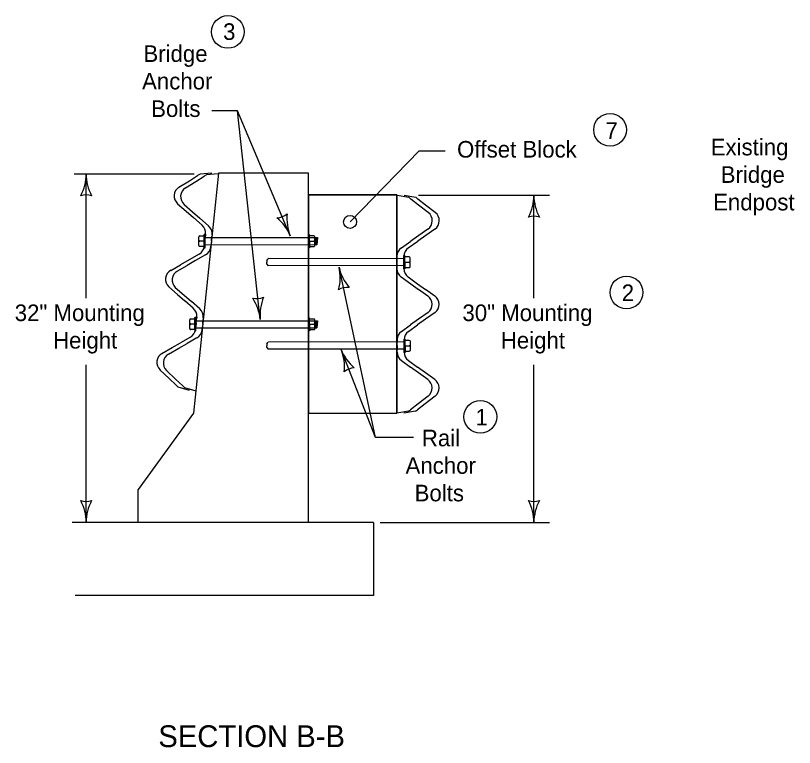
# Model space of a CAD drawing. Extents: x -2137026 to -2131464, y -2138478 to -2136524.
# Drawn here: x -2136255 to -2135542, y -2137286 to -2136616 of the extents above; entities that cross this region are included whole.
import ezdxf

# ---------------------------------------------------------------- set-up
doc = ezdxf.new("R2010")
doc.units = 0
for name, color, linetype in [('conPaving', 7, 'Continuous'), ('Level 2', 7, 'Continuous'), ('Level 3', 7, 'Continuous'), ('Level 9', 7, 'Continuous')]:
    doc.layers.add(name, color=color, linetype=linetype)

msp = doc.modelspace()

# ---------------------------------------------------------------- linework, layer by layer
at = {"layer": 'conPaving'}
for p, q in [((-2135980.49, -2136818.99), (-2135980.97, -2136825.47)), ((-2135979.93, -2136818.99), (-2135980.42, -2136825.47)), ((-2135979.38, -2136818.99), (-2135979.86, -2136825.47)), ((-2135978.82, -2136818.99), (-2135979.31, -2136825.47)), ((-2135980.52, -2136895.16), (-2135981, -2136901.64)), ((-2135979.96, -2136895.16), (-2135980.44, -2136901.64)), ((-2135979.4, -2136895.16), (-2135979.89, -2136901.64)), ((-2135978.89, -2136895.16), (-2135979.37, -2136901.64))]:
    msp.add_line(p, q, dxfattribs=at)
at = {"layer": 'Level 2'}
for p, q in [((-2136051.92, -2136702.87), (-2136075.52, -2136702.87)), ((-2136003.7, -2136817.5), (-2136051.92, -2136702.87)), ((-2136031.2, -2136893.97), (-2136051.92, -2136702.87)), ((-2135949.03, -2136804.59), (-2135885.58, -2136739.51)), ((-2135885.58, -2136739.51), (-2135861.94, -2136739.51)), ((-2136201.65, -2136760.66), (-2136091.76, -2136760.66)), ((-2136096.13, -2136766.92), (-2136088.57, -2136762.19)), ((-2136086.33, -2136760.79), (-2136088.57, -2136762.19)), ((-2136075.62, -2136760.02), (-2136086.33, -2136760.79)), ((-2136080.36, -2136761.42), (-2136082.6, -2136762.82)), ((-2136069.65, -2136760.65), (-2136080.36, -2136761.42)), ((-2136190.58, -2136874.42), (-2136190.58, -2136766.56)), ((-2136105.65, -2136772.86), (-2136096.13, -2136766.92)), ((-2136099.68, -2136773.49), (-2136090.16, -2136767.54)), ((-2136090.16, -2136767.54), (-2136082.6, -2136762.82)), ((-2135905.88, -2136780.11), (-2135895.3, -2136782)), ((-2135899.48, -2136780.11), (-2135888.9, -2136782)), ((-2135895.3, -2136782), (-2135893.22, -2136783.62)), ((-2135886.19, -2136789.11), (-2135893.22, -2136783.62)), ((-2135888.9, -2136782), (-2135886.82, -2136783.62)), ((-2135879.79, -2136789.11), (-2135886.82, -2136783.62)), ((-2135886.21, -2136780.2), (-2135766.29, -2136780.2)), ((-2135780.7, -2136874.42), (-2135780.7, -2136780.2)), ((-2136106.88, -2136787.91), (-2136099.12, -2136794.75)), ((-2136100.92, -2136788.54), (-2136093.15, -2136795.38)), ((-2135877.34, -2136796.01), (-2135886.19, -2136789.11)), ((-2135870.94, -2136796.01), (-2135879.79, -2136789.11)), ((-2136099.12, -2136794.75), (-2136092.43, -2136800.64)), ((-2136093.15, -2136795.38), (-2136086.46, -2136801.26)), ((-2136084.45, -2136807.66), (-2136092.43, -2136800.64)), ((-2136078.48, -2136808.29), (-2136086.46, -2136801.26)), ((-2135877.68, -2136811.11), (-2135886.12, -2136817.1)), ((-2135871.28, -2136811.11), (-2135879.72, -2136817.1)), ((-2136081.87, -2136821.31), (-2136081.48, -2136817.44)), ((-2136081.3, -2136815.68), (-2136081.48, -2136817.44)), ((-2136075.9, -2136821.94), (-2136075.51, -2136818.06)), ((-2136075.33, -2136816.31), (-2136075.51, -2136818.06)), ((-2135886.12, -2136817.1), (-2135893.38, -2136822.26)), ((-2135879.72, -2136817.1), (-2135886.99, -2136822.26)), ((-2136082.45, -2136826.94), (-2136082.24, -2136824.91)), ((-2136081.86, -2136821.17), (-2136082.24, -2136824.91)), ((-2136076.48, -2136827.57), (-2136076.27, -2136825.53)), ((-2136075.89, -2136821.8), (-2136076.27, -2136825.53)), ((-2135902.05, -2136828.41), (-2135893.38, -2136822.26)), ((-2135895.65, -2136828.41), (-2135886.99, -2136822.26)), ((-2136096.37, -2136839.42), (-2136104.1, -2136843.83)), ((-2136090.4, -2136840.04), (-2136098.14, -2136844.46)), ((-2136087.15, -2136834.16), (-2136096.37, -2136839.42)), ((-2136081.19, -2136834.79), (-2136090.4, -2136840.04)), ((-2135906.03, -2136841.72), (-2135906.02, -2136837.83)), ((-2135906.02, -2136836.06), (-2135906.02, -2136837.83)), ((-2135899.64, -2136841.72), (-2135899.63, -2136837.83)), ((-2135899.62, -2136836.06), (-2135899.63, -2136837.83)), ((-2136113.12, -2136848.97), (-2136104.1, -2136843.83)), ((-2136107.15, -2136849.6), (-2136098.14, -2136844.46)), ((-2135925.73, -2137002.21), (-2135959.06, -2136846.16)), ((-2135906.05, -2136847.38), (-2135906.04, -2136845.33)), ((-2135906.03, -2136841.58), (-2135906.04, -2136845.33)), ((-2135899.64, -2136841.58), (-2135899.65, -2136845.33)), ((-2135899.65, -2136847.38), (-2135899.65, -2136845.33)), ((-2135902.12, -2136855.05), (-2135893.5, -2136861.24)), ((-2135895.72, -2136855.05), (-2135887.1, -2136861.24)), ((-2135893.5, -2136861.24), (-2135886.26, -2136866.43)), ((-2135887.1, -2136861.24), (-2135879.87, -2136866.43)), ((-2136114.93, -2136863.98), (-2136106.88, -2136871.06)), ((-2136108.96, -2136864.61), (-2136100.91, -2136871.69)), ((-2135877.84, -2136872.48), (-2135886.26, -2136866.43)), ((-2135871.44, -2136872.48), (-2135879.87, -2136866.43)), ((-2136106.88, -2136871.06), (-2136100.19, -2136876.95)), ((-2136100.91, -2136871.69), (-2136094.23, -2136877.58)), ((-2136092.49, -2136883.73), (-2136100.19, -2136876.95)), ((-2136086.52, -2136884.36), (-2136094.23, -2136877.58)), ((-2135877.6, -2136887.6), (-2135886.34, -2136893.81)), ((-2135871.2, -2136887.6), (-2135879.94, -2136893.81)), ((-2136089.88, -2136897.07), (-2136090.26, -2136900.8)), ((-2136089.88, -2136897.07), (-2136089.5, -2136893.33)), ((-2136089.34, -2136891.75), (-2136089.5, -2136893.33)), ((-2136083.91, -2136897.69), (-2136084.29, -2136901.42)), ((-2136083.91, -2136897.69), (-2136083.53, -2136893.96)), ((-2136083.37, -2136892.38), (-2136083.53, -2136893.96)), ((-2135886.34, -2136893.81), (-2135893.6, -2136898.96)), ((-2135879.94, -2136893.81), (-2135887.2, -2136898.96)), ((-2136090.49, -2136903.01), (-2136090.26, -2136900.8)), ((-2136084.52, -2136903.64), (-2136084.29, -2136901.42)), ((-2135901.97, -2136904.91), (-2135893.6, -2136898.97)), ((-2135895.57, -2136904.91), (-2135887.2, -2136898.97)), ((-2136095.2, -2136910.23), (-2136104.11, -2136915.32)), ((-2136089.23, -2136910.86), (-2136098.15, -2136915.94)), ((-2136111.85, -2136919.73), (-2136104.11, -2136915.32)), ((-2136105.89, -2136920.36), (-2136098.15, -2136915.94)), ((-2135905.95, -2136917.9), (-2135905.96, -2136921.65)), ((-2135905.95, -2136917.9), (-2135905.94, -2136914.14)), ((-2135905.94, -2136912.56), (-2135905.94, -2136914.14)), ((-2135899.56, -2136917.9), (-2135899.57, -2136921.65)), ((-2135899.56, -2136917.9), (-2135899.55, -2136914.14)), ((-2135899.54, -2136912.56), (-2135899.55, -2136914.14)), ((-2136121.16, -2136925.04), (-2136111.85, -2136919.73)), ((-2136115.19, -2136925.67), (-2136105.89, -2136920.36)), ((-2135925.73, -2137002.21), (-2135957.16, -2136921.59)), ((-2135905.97, -2136923.87), (-2135905.96, -2136921.65)), ((-2135899.57, -2136923.87), (-2135899.57, -2136921.65)), ((-2135902.04, -2136931.54), (-2135893.7, -2136937.53)), ((-2135895.64, -2136931.54), (-2135887.3, -2136937.53)), ((-2136190.58, -2137079.91), (-2136190.58, -2136935.43)), ((-2136122.99, -2136940.03), (-2136114.62, -2136948.01)), ((-2136117.03, -2136940.65), (-2136108.66, -2136948.63)), ((-2135886.46, -2136942.73), (-2135893.7, -2136937.53)), ((-2135880.06, -2136942.73), (-2135887.3, -2136937.53)), ((-2135780.7, -2137079.91), (-2135780.7, -2136935.43)), ((-2136114.62, -2136948.01), (-2136108.17, -2136954.17)), ((-2135877.76, -2136948.98), (-2135886.46, -2136942.73)), ((-2135871.36, -2136948.98), (-2135880.06, -2136942.73)), ((-2136108.66, -2136948.63), (-2136102.2, -2136954.79)), ((-2136106.51, -2136955.75), (-2136108.17, -2136954.17)), ((-2136100.54, -2136956.38), (-2136102.2, -2136954.79)), ((-2136106.51, -2136955.75), (-2136096.17, -2136958.67)), ((-2136100.54, -2136956.38), (-2136090.2, -2136959.3)), ((-2135877.49, -2136964.07), (-2135886.64, -2136971.14)), ((-2135871.09, -2136964.07), (-2135880.25, -2136971.14)), ((-2135895.53, -2136978), (-2135893.7, -2136976.59)), ((-2135886.64, -2136971.14), (-2135893.7, -2136976.59)), ((-2135889.13, -2136978), (-2135887.31, -2136976.59)), ((-2135880.25, -2136971.14), (-2135887.31, -2136976.59)), ((-2135895.53, -2136978), (-2135906.11, -2136979.83)), ((-2135889.13, -2136978), (-2135899.71, -2136979.83)), ((-2135890.85, -2137002.21), (-2135925.73, -2137002.21)), ((-2135921.36, -2137079.91), (-2135766.29, -2137079.91))]:
    msp.add_line(p, q, dxfattribs=at)
for centre in [(-2136060.85, -2136630.59), (-2135710.97, -2136720.21), (-2135695.91, -2136869.2), (-2135829.72, -2136983.12)]:
    msp.add_circle(centre, 15, dxfattribs=at)
for centre, radius, start, end in [((-2136233.08, -2136760.66), 42.5, 331.92751, 360), ((-2136148.08, -2136760.66), 42.5, 180, 208.07249), ((-2136190.58, -2136796.29), 16.42, 72.26665, 107.73335), ((-2135823.2, -2136780.2), 42.5, 331.92751, 360), ((-2135738.2, -2136780.2), 42.5, 180, 208.07249), ((-2136017.15, -2136784.5), 16.42, 274.42912, 309.89582), ((-2135964.34, -2136801.47), 42.5, 174.08998, 202.16247), ((-2136043.06, -2136833.54), 42.5, 22.16247, 50.23496), ((-2135780.7, -2136815.83), 16.42, 72.26665, 107.73335), ((-2136000.54, -2136855.44), 42.5, 344.5421, 12.61459), ((-2135917.59, -2136836.88), 42.5, 192.61459, 220.68708), ((-2135951.28, -2136880.94), 16.42, 84.88124, 120.34794), ((-2136034.64, -2136858.5), 16.42, 257.8046, 293.2713), ((-2136073.5, -2136898.07), 42.5, 5.53795, 33.61044), ((-2135988.9, -2136889.86), 42.5, 157.46546, 185.53795), ((-2135996.61, -2136937.41), 42.5, 353.78289, 21.85538), ((-2135917.72, -2136905.76), 42.5, 201.85538, 229.92787), ((-2135943.9, -2136954.66), 16.42, 94.12203, 129.58873), ((-2136190.58, -2137044.27), 16.42, 252.26665, 287.73335), ((-2136233.08, -2137079.91), 42.5, 360, 28.07249), ((-2136148.08, -2137079.91), 42.5, 151.92751, 180), ((-2135780.7, -2137044.27), 16.42, 252.26665, 287.73335), ((-2135823.2, -2137079.91), 42.5, 360, 28.07249), ((-2135738.2, -2137079.91), 42.5, 151.92751, 180)]:
    msp.add_arc(centre, radius, start, end, dxfattribs=at)
for centre, major_axis, start_param, end_param in [((-2136100.61, -2136780.85), (9.43, -0.96), 2.229659, 4.096128), ((-2136094.64, -2136781.48), (9.43, -0.96), 2.229659, 4.096128), ((-2135883.19, -2136803.43), (-9.48, 0.02), 2.187057, 4.053527), ((-2135876.79, -2136803.43), (-9.48, 0.02), 2.187057, 4.053527), ((-2136090.73, -2136814.72), (9.43, -0.96), 0, 0.954538), ((-2136084.76, -2136815.35), (9.43, -0.96), 0, 0.954538), ((-2136091.87, -2136825.98), (-9.43, 0.96), 2.187055, 3.141593), ((-2136085.91, -2136826.6), (-9.43, 0.96), 2.187055, 3.141593), ((-2135896.54, -2136836.09), (-9.48, 0.02), 5.328647, 6.283185), ((-2135890.14, -2136836.09), (-9.48, 0.02), 5.328647, 6.283185), ((-2135896.57, -2136847.41), (9.48, -0.02), 3.141593, 4.096131), ((-2135890.17, -2136847.41), (9.48, -0.02), 3.141593, 4.096131), ((-2136108.4, -2136857.15), (-9.43, 0.96), 5.32865, 7.195119), ((-2136102.43, -2136857.78), (-9.43, 0.96), 5.32865, 7.195119), ((-2135883.38, -2136880.13), (9.48, -0.02), 5.371251, 7.237721), ((-2135876.99, -2136880.13), (9.48, -0.02), 5.371251, 7.237721), ((-2136098.77, -2136890.79), (9.43, -0.96), 0, 0.954538), ((-2136092.8, -2136891.42), (9.43, -0.96), 0, 0.954538), ((-2136099.92, -2136902.05), (-9.43, 0.96), 2.187055, 3.141593), ((-2136093.95, -2136902.67), (-9.43, 0.96), 2.187055, 3.141593), ((-2135896.46, -2136912.58), (-9.48, 0.02), 5.328647, 6.283185), ((-2135890.06, -2136912.58), (-9.48, 0.02), 5.328647, 6.283185), ((-2136116.44, -2136933.22), (-9.43, 0.96), 5.32865, 7.195119), ((-2136110.47, -2136933.85), (-9.43, 0.96), 5.32865, 7.195119), ((-2135896.49, -2136923.9), (9.48, -0.02), 3.141593, 4.096131), ((-2135890.09, -2136923.9), (9.48, -0.02), 3.141593, 4.096131), ((-2135883.3, -2136956.62), (9.48, -0.02), 5.371251, 7.237721), ((-2135876.91, -2136956.62), (9.48, -0.02), 5.371251, 7.237721)]:
    msp.add_ellipse(centre, major_axis=major_axis, ratio=0.994906, start_param=start_param, end_param=end_param, dxfattribs=at)
at = {"layer": 'Level 3'}
for p, q in [((-2136069.5, -2136760.02), (-2136092.33, -2136979.8)), ((-2135986.92, -2136760.02), (-2136069.5, -2136760.02)), ((-2135986.92, -2137079.8), (-2135986.92, -2136760.02)), ((-2136092.33, -2136979.8), (-2136142.9, -2137049.8)), ((-2136142.9, -2137079.8), (-2136142.9, -2137049.8))]:
    msp.add_line(p, q, dxfattribs=at)
at = {"layer": 'Level 9'}
for p, q in [((-2135986.92, -2136779.9), (-2135906.03, -2136779.9)), ((-2135906.03, -2136779.9), (-2135986.92, -2136779.9)), ((-2135986.92, -2136779.9), (-2135986.92, -2136979.9)), ((-2135906.03, -2136979.9), (-2135906.03, -2136779.9)), ((-2135906.03, -2136779.9), (-2135906.03, -2136979.9)), ((-2136087.41, -2136822.99), (-2136087.41, -2136818.13)), ((-2136086.45, -2136817.26), (-2136082.61, -2136817.27)), ((-2136082.62, -2136826.99), (-2136082.61, -2136817.27)), ((-2136082.61, -2136822.13), (-2136082.61, -2136816.05)), ((-2136081.71, -2136816.05), (-2136082.61, -2136816.05)), ((-2136081.72, -2136828.2), (-2136081.71, -2136816.05)), ((-2136081.71, -2136822.13), (-2136081.71, -2136818.89)), ((-2136081.71, -2136818.89), (-2135978.82, -2136818.99)), ((-2135986.92, -2136816.15), (-2135986.02, -2136816.14)), ((-2135986.91, -2136828.3), (-2135986.92, -2136816.15)), ((-2135986.91, -2136822.22), (-2135986.92, -2136818.98)), ((-2135986.01, -2136822.22), (-2135986.02, -2136816.14)), ((-2135986.01, -2136827.08), (-2135986.02, -2136817.36)), ((-2135982.18, -2136817.36), (-2135986.02, -2136817.36)), ((-2135981.21, -2136823.08), (-2135981.22, -2136818.22)), ((-2136087.42, -2136826.12), (-2136087.41, -2136822.99)), ((-2136082.61, -2136822.13), (-2136086.45, -2136822.12)), ((-2136082.61, -2136822.13), (-2136082.62, -2136828.2)), ((-2136081.7, -2136825.37), (-2135979.31, -2136825.47)), ((-2135986.01, -2136822.22), (-2135986.01, -2136828.29)), ((-2135986.01, -2136822.22), (-2135982.17, -2136822.22)), ((-2135981.21, -2136826.21), (-2135981.21, -2136823.08)), ((-2136082.62, -2136826.99), (-2136086.46, -2136826.98)), ((-2136082.62, -2136828.2), (-2136081.72, -2136828.2)), ((-2135986.01, -2136828.29), (-2135986.91, -2136828.3)), ((-2135986.01, -2136827.08), (-2135982.17, -2136827.08)), ((-2136025.24, -2136839.94), (-2136025.25, -2136841.56)), ((-2136025.24, -2136839.94), (-2136024.06, -2136838.32)), ((-2135899.63, -2136838.34), (-2136023.93, -2136838.13)), ((-2135899.65, -2136847.66), (-2135899.63, -2136835.51)), ((-2135899.64, -2136841.58), (-2135899.63, -2136838.34)), ((-2135899.63, -2136835.51), (-2135898.73, -2136835.51)), ((-2135898.74, -2136841.58), (-2135898.73, -2136835.51)), ((-2135898.74, -2136846.44), (-2135898.73, -2136836.72)), ((-2135894.89, -2136836.73), (-2135898.73, -2136836.72)), ((-2135893.94, -2136842.46), (-2135893.93, -2136837.6)), ((-2136025.25, -2136843.18), (-2136025.25, -2136841.56)), ((-2136025.25, -2136843.18), (-2136024.07, -2136844.8)), ((-2135899.64, -2136844.82), (-2136024.21, -2136844.61)), ((-2135898.75, -2136847.66), (-2135899.65, -2136847.66)), ((-2135898.74, -2136841.58), (-2135898.75, -2136847.66)), ((-2135898.74, -2136841.58), (-2135894.9, -2136841.59)), ((-2135898.74, -2136846.44), (-2135894.9, -2136846.45)), ((-2135893.94, -2136845.59), (-2135893.94, -2136842.46)), ((-2136095.81, -2136899.16), (-2136095.81, -2136894.3)), ((-2136094.85, -2136893.44), (-2136091.01, -2136893.44)), ((-2136091.02, -2136903.16), (-2136091.01, -2136893.44)), ((-2136091.01, -2136898.3), (-2136091.01, -2136892.23)), ((-2136090.11, -2136892.23), (-2136091.01, -2136892.23)), ((-2136090.12, -2136904.38), (-2136090.11, -2136892.23)), ((-2136090.11, -2136898.3), (-2136090.11, -2136895.06)), ((-2136090.11, -2136895.07), (-2135978.89, -2136895.16)), ((-2135986.91, -2136904.47), (-2135986.92, -2136892.32)), ((-2135986.92, -2136892.32), (-2135986.02, -2136892.32)), ((-2135986.91, -2136898.4), (-2135986.92, -2136895.16)), ((-2135986.01, -2136898.39), (-2135986.02, -2136892.32)), ((-2135986.01, -2136903.25), (-2135986.02, -2136893.53)), ((-2135982.18, -2136893.53), (-2135986.02, -2136893.53)), ((-2135981.21, -2136899.25), (-2135981.22, -2136894.39)), ((-2136095.82, -2136902.29), (-2136095.81, -2136899.16)), ((-2136091.02, -2136903.16), (-2136094.86, -2136903.16)), ((-2136091.01, -2136898.3), (-2136094.85, -2136898.3)), ((-2136091.01, -2136898.3), (-2136091.02, -2136904.38)), ((-2136091.02, -2136904.38), (-2136090.12, -2136904.38)), ((-2136090.1, -2136901.55), (-2135979.37, -2136901.64)), ((-2135986.01, -2136904.47), (-2135986.91, -2136904.47)), ((-2135986.01, -2136898.39), (-2135986.01, -2136904.47)), ((-2135986.01, -2136898.39), (-2135982.17, -2136898.39)), ((-2135986.01, -2136903.25), (-2135982.17, -2136903.25)), ((-2135981.21, -2136902.39), (-2135981.21, -2136899.25)), ((-2135899.52, -2136924.12), (-2135899.5, -2136911.97)), ((-2135899.5, -2136911.97), (-2135898.6, -2136911.97)), ((-2135898.61, -2136918.04), (-2135898.6, -2136911.97)), ((-2136025.11, -2136916.4), (-2136025.12, -2136918.02)), ((-2136025.12, -2136919.64), (-2136025.12, -2136918.02)), ((-2136025.11, -2136916.4), (-2136023.93, -2136914.78)), ((-2135899.5, -2136914.8), (-2136023.8, -2136914.59)), ((-2135899.51, -2136918.04), (-2135899.5, -2136914.8)), ((-2135898.61, -2136918.04), (-2135898.62, -2136924.12)), ((-2135898.61, -2136922.9), (-2135898.6, -2136913.18)), ((-2135898.61, -2136918.04), (-2135894.77, -2136918.05)), ((-2135894.76, -2136913.19), (-2135898.6, -2136913.18)), ((-2135893.81, -2136918.91), (-2135893.8, -2136914.05)), ((-2135893.81, -2136922.05), (-2135893.81, -2136918.91)), ((-2136025.12, -2136919.64), (-2136023.94, -2136921.26)), ((-2135899.51, -2136921.28), (-2136024.08, -2136921.07)), ((-2135898.62, -2136924.12), (-2135899.52, -2136924.12)), ((-2135898.61, -2136922.9), (-2135894.77, -2136922.91)), ((-2135986.92, -2136979.9), (-2135906.03, -2136979.9)), ((-2135986.92, -2136979.9), (-2135906.03, -2136979.9)), ((-2135927.51, -2137079.91), (-2136203.36, -2137079.91)), ((-2135927.51, -2137079.91), (-2135927.51, -2137146.9)), ((-2135927.51, -2137146.9), (-2136200.54, -2137146.9))]:
    msp.add_line(p, q, dxfattribs=at)
msp.add_circle((-2135949.03, -2136804.59), 5.96, dxfattribs=at)
for centre, major_axis, start_param, end_param in [((-2136086.45, -2136818.13), (-0.96, 0.001), 4.712389, 6.283185), ((-2135982.18, -2136818.22), (-0.96, -0.001), 3.141593, 4.712389), ((-2136086.46, -2136826.12), (-0.96, 0.001), 6.283185, 7.853982), ((-2136086.45, -2136821.26), (-0.96, 0.001), 0, 1.570796), ((-2136086.45, -2136822.99), (-0.96, 0.001), 4.712389, 6.283185), ((-2135982.17, -2136821.35), (-0.96, -0.001), 1.570796, 3.141593), ((-2135982.17, -2136823.08), (-0.96, -0.001), 3.141593, 4.712389), ((-2135982.17, -2136826.21), (-0.96, -0.001), 1.570796, 3.141593), ((-2135894.89, -2136840.73), (-0.96, 0.002), 1.570796, 3.141593), ((-2135894.89, -2136837.59), (-0.96, 0.002), 3.141593, 4.712389), ((-2135894.9, -2136842.45), (-0.96, 0.002), 3.141593, 4.712389), ((-2135894.9, -2136845.59), (-0.96, 0.002), 1.570796, 3.141593), ((-2136094.85, -2136894.3), (-0.96, 0.001), 4.712389, 6.283185), ((-2136094.85, -2136897.43), (-0.96, 0.001), 0, 1.570796), ((-2135982.18, -2136894.4), (-0.96, -0.001), 3.141593, 4.712389), ((-2135982.17, -2136897.53), (-0.96, -0.001), 1.570796, 3.141593), ((-2136094.86, -2136902.29), (-0.96, 0.001), 6.283185, 7.853982), ((-2136094.85, -2136899.16), (-0.96, 0.001), 4.712389, 6.283185), ((-2135982.17, -2136899.26), (-0.96, -0.001), 3.141593, 4.712389), ((-2135982.17, -2136902.39), (-0.96, -0.001), 1.570796, 3.141593), ((-2135894.77, -2136917.18), (-0.96, 0.002), 1.570796, 3.141593), ((-2135894.77, -2136918.91), (-0.96, 0.002), 3.141593, 4.712389), ((-2135894.76, -2136914.05), (-0.96, 0.002), 3.141593, 4.712389), ((-2135894.77, -2136922.04), (-0.96, 0.002), 1.570796, 3.141593)]:
    msp.add_ellipse(centre, major_axis=major_axis, ratio=0.899999, start_param=start_param, end_param=end_param, dxfattribs=at)

# ---------------------------------------------------------------- texts
at = {"layer": 'Level 2'}
for s, p in [('3', (-2136065.22, -2136637.88)), ('7', (-2135715.18, -2136728.57)), ('2', (-2135700.28, -2136877.11)), ('1', (-2135834.09, -2136991.03))]:
    msp.add_text(s, height=15.2, dxfattribs=at).set_placement(p)
at = {"layer": 'Level 3'}
for s, height, p in [('Bridge', 15.2, (-2136138.18, -2136658.05)), ('Anchor', 15.2, (-2136139.41, -2136683.25)), ('Bolts', 15.2, (-2136131.09, -2136708.45)), ('Offset Block', 15.2, (-2135851.03, -2136745.67)), ('Existing', 15.2, (-2135618.84, -2136743.63)), ('Bridge', 15.2, (-2135609.68, -2136768.83)), ('Endpost', 15.2, (-2135616.62, -2136794.03)), ('32" Mounting', 15.2, (-2136255.98, -2136895.44)), ('30" Mounting', 15.2, (-2135846.1, -2136895.44)), ('Height', 15.2, (-2136220.87, -2136920.64)), ('Height', 15.2, (-2135810.99, -2136920.64)), ('Rail', 15.2, (-2135883.27, -2137010.13)), ('Anchor', 15.2, (-2135898.2, -2137035.33)), ('Bolts', 15.2, (-2135889.89, -2137060.53)), ('SECTION B-B', 20, (-2136124.54, -2137285.68))]:
    msp.add_text(s, height=height, dxfattribs=at).set_placement(p)

doc.saveas('drawing.dxf')
